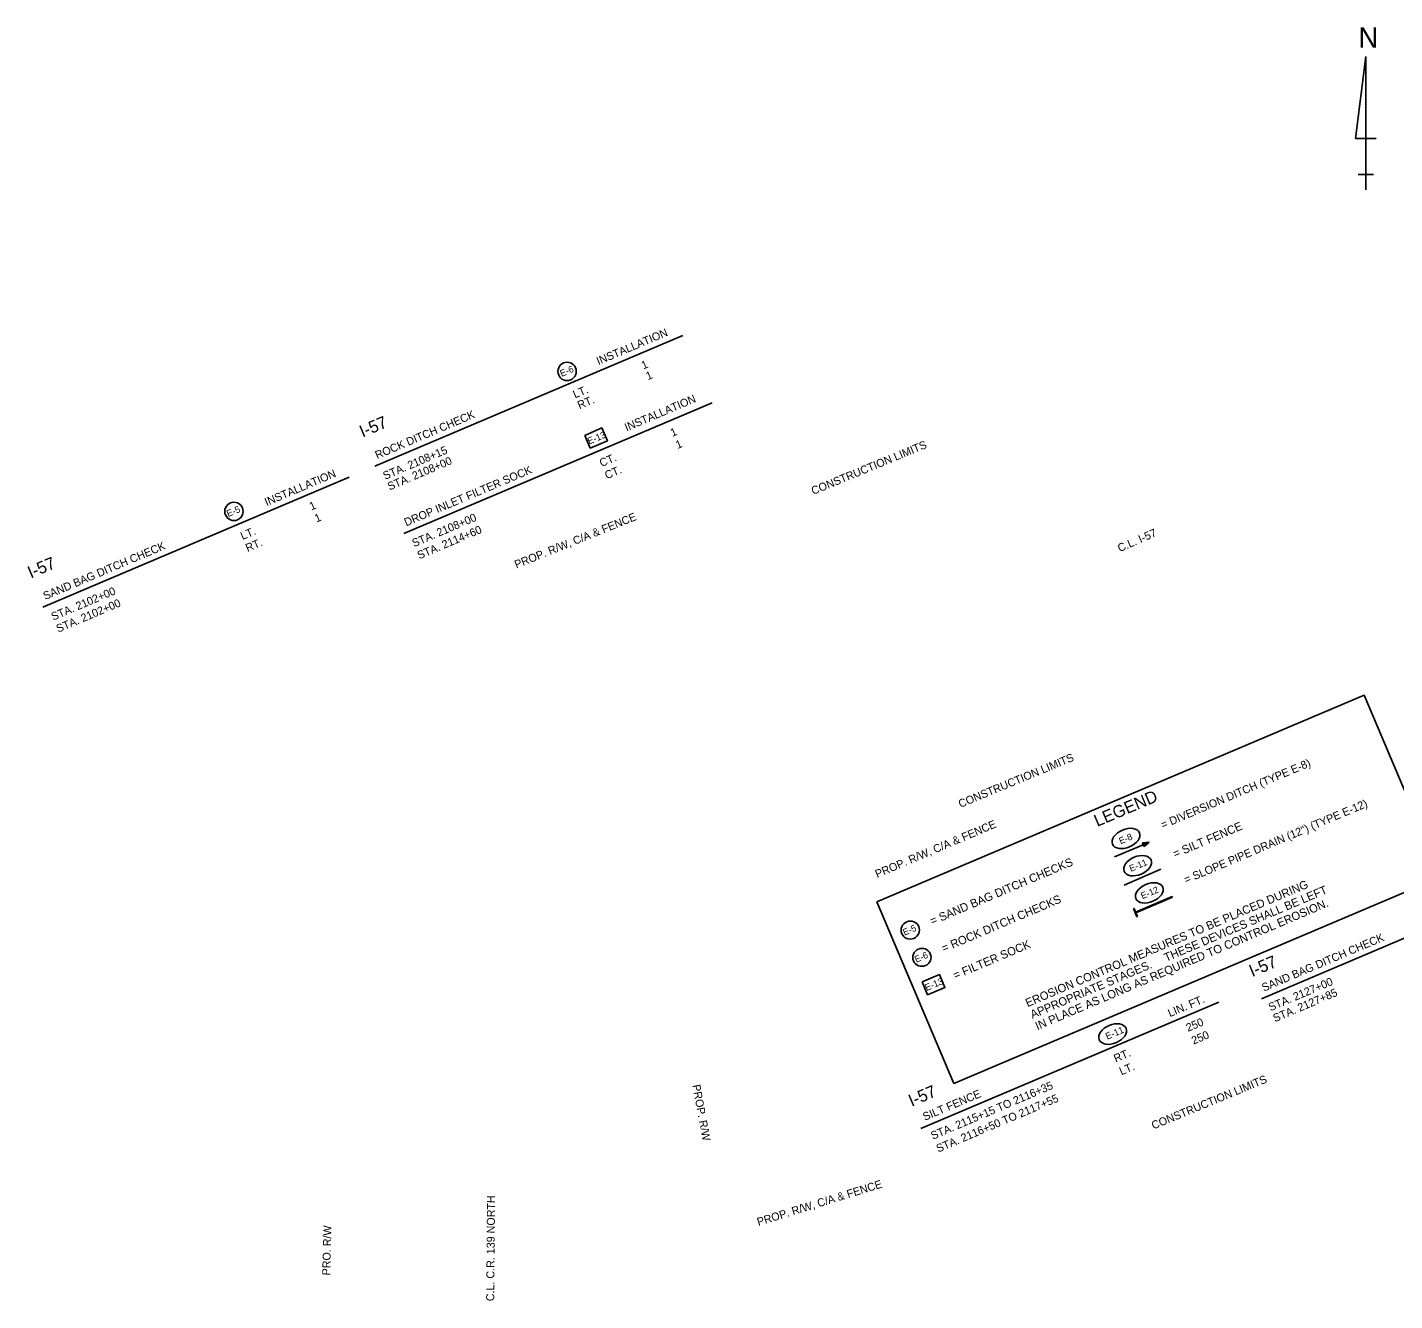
# Model space of a CAD drawing. Extents: x 1716086 to 1717910, y 765525 to 766719.
# Drawn here: x 1716086 to 1717110, y 765586 to 766541 of the extents above; entities that cross this region are included whole.
import ezdxf

# ---------------------------------------------------------------- set-up
doc = ezdxf.new("R2010")
doc.units = 0
for name, color, linetype in [('1', 7, 'Continuous'), ('44', 7, 'Continuous'), ('63', 7, 'Continuous'), ('Level 1', 7, 'Continuous'), ('Level 44', 7, 'Continuous'), ('R_Draft', 7, 'Continuous')]:
    doc.layers.add(name, color=color, linetype=linetype)

msp = doc.modelspace()

# ---------------------------------------------------------------- linework, layer by layer
at = {"layer": '1'}
for points in [[(1716503.3, 766234.8), (1716516.2, 766240.3), (1716520.3, 766230.7), (1716507.4, 766225.2)], [(1716722.2, 765885.1), (1717087.4, 766040.1), (1717145.2, 765903.9), (1716780, 765749)], [(1716756.2, 765825.1), (1716769.1, 765830.6), (1716773.2, 765821), (1716760.3, 765815.5)]]:
    msp.add_lwpolyline(points, close=True, dxfattribs=at)
for centre in [(1716490.1, 766282.7), (1716240.4, 766177.8)]:
    msp.add_circle(centre, 6.88, dxfattribs=at)
msp.add_ellipse((1716899, 765786), major_axis=(10.1, 4.3), ratio=0.638788, dxfattribs=at)
at = {"layer": '44'}
for p, q in [((1716345.9, 766211.7), (1716576.9, 766309.7)), ((1716367.7, 766161.2), (1716598.7, 766259.2)), ((1716097.1, 766106), (1716326.8, 766203.5)), ((1717010.5, 765812.4), (1717240.2, 765909.9)), ((1716755.2, 765715.2), (1716978.5, 765809.9))]:
    msp.add_line(p, q, dxfattribs=at)
at = {"layer": '63'}
for p, q in [((1717088.8, 766518.8), (1717081.1, 766457.3)), ((1717088.8, 766418.8), (1717088.8, 766518.8)), ((1717088.8, 766518.8), (1717088.8, 766441.9)), ((1717081.1, 766457.3), (1717096.5, 766457.3)), ((1717088.8, 766418.8), (1717088.8, 766441.9)), ((1717088.8, 766430.4), (1717083.1, 766430.4)), ((1717083.1, 766430.4), (1717094.6, 766430.4)), ((1717088.8, 766418.8), (1717088.8, 766430.4))]:
    msp.add_line(p, q, dxfattribs=at)
at = {"layer": 'Level 1'}
for p, q in [((1716926.4, 765929.8), (1716921.4, 765929.3)), ((1716921.4, 765929.3), (1716922.5, 765926.6)), ((1716925.1, 765929.6), (1716921.6, 765928.9)), ((1716925.2, 765929.5), (1716921.7, 765928.6)), ((1716925.2, 765929.4), (1716921.8, 765928.3)), ((1716922.1, 765927.6), (1716925.3, 765929.2)), ((1716922.3, 765927.3), (1716925.3, 765929.2)), ((1716922.4, 765927), (1716925.4, 765929.1)), ((1716922.5, 765926.6), (1716926.4, 765929.8))]:
    msp.add_line(p, q, dxfattribs=at)
msp.add_lwpolyline([(1716900.4, 765918.8), (1716924.8, 765929.2)], dxfattribs=at)
for centre, major_axis, ratio in [((1716909, 765932.6), (10.1, 4.3), 0.622952), ((1716917.7, 765912.2), (10.1, 4.3), 0.622952), ((1716926.5, 765891.8), (10.1, 4.3), 0.622952), ((1716747.3, 765863.9), (-6.33, -2.69), 0.97521), ((1716756, 765843.5), (-6.33, -2.69), 0.97521)]:
    msp.add_ellipse(centre, major_axis=major_axis, ratio=ratio, dxfattribs=at)
at = {"layer": 'Level 44'}
for p, q in [((1716943.7, 765889), (1716916.2, 765877.3)), ((1716943.9, 765888.5), (1716916.4, 765876.8)), ((1716943.7, 765889), (1716943.9, 765888.5)), ((1716914.5, 765880), (1716915, 765880.2)), ((1716917.1, 765873.8), (1716914.5, 765880)), ((1716916.2, 765877.3), (1716915, 765880.2)), ((1716917.6, 765874), (1716916.4, 765876.8)), ((1716917.1, 765873.8), (1716917.6, 765874))]:
    msp.add_line(p, q, dxfattribs=at)
msp.add_lwpolyline([(1716907.5, 765897.7), (1716935.2, 765909.5)], dxfattribs=at)

# ---------------------------------------------------------------- texts
at = {"layer": '1'}
for s, rotation, p in [('E-6 ', 23, (1716486, 766278.6)), ('E-13', 22.6177, (1716506.6, 766227.9)), ('E-5 ', 23, (1716236.1, 766173.5)), ('E-13', 22.6177, (1716759.5, 765818.2)), ('E-11', 23, (1716894.9, 765781.7))]:
    msp.add_text(s, height=5, rotation=rotation, dxfattribs=at).set_placement(p)
at = {"layer": '44'}
for s, p in [('INSTALLATION', (1716513.6, 766287.4)), ('1', (1716547.2, 766284.1)), ('1', (1716550.6, 766276.1)), ('LT.', (1716496, 766262.4)), ('INSTALLATION', (1716534.7, 766237.7)), ('RT.', (1716499.4, 766254.3)), ('ROCK DITCH CHECK', (1716347.7, 766216.9)), ('1', (1716569, 766233.6)), ('STA. 2108+15', (1716353.6, 766201.4)), ('1', (1716572.9, 766224.5)), ('STA. 2108+00', (1716357, 766193.4)), ('CT.', (1716515.9, 766211)), ('INSTALLATION', (1716264.9, 766181.7)), ('DROP INLET FILTER SOCK', (1716369.5, 766166.5)), ('CT.', (1716519.8, 766201.8)), ('1', (1716298.4, 766178.4)), ('1', (1716302.3, 766169.4)), ('STA. 2108+00', (1716375.4, 766150.9)), ('LT.', (1716246.8, 766156.3)), ('STA. 2114+60', (1716379.3, 766141.8)), ('SAND BAG DITCH CHECK', (1716098.9, 766111.3)), ('RT.', (1716250.6, 766147.3)), ('STA. 2102+00', (1716104.9, 766095.8)), ('STA. 2102+00', (1716108.7, 766086.8)), ('SAND BAG DITCH CHECK', (1717012.3, 765817.7)), ('STA. 2127+00', (1717017.3, 765803)), ('LIN. FT.', (1716941.9, 765798.6)), ('STA. 2127+85', (1717020.7, 765794.8)), ('250', (1716955.5, 765787.6)), ('250', (1716959.6, 765778)), ('RT.', (1716901.3, 765764.6)), ('LT.', (1716905.5, 765755)), ('SILT FENCE      ', (1716758.2, 765720.9)), ('STA. 2115+15 TO 2116+35', (1716764.2, 765706.7)), ('STA. 2116+50 TO 2117+55', (1716768.3, 765697.1))]:
    msp.add_text(s, height=6, rotation=23, dxfattribs=at).set_placement(p)
at = {"layer": '63'}
msp.add_text('N', height=15.4, rotation=360, dxfattribs=at).set_placement((1717083.2, 766525.3))
at = {"layer": 'Level 1'}
for s, height, rotation, p in [('= DIVERSION DITCH (TYPE E-8)', 6, 23, (1716936.6, 765939.7)), ('= SLOPE PIPE DRAIN (12") (TYPE E-12)', 6, 23, (1716954, 765898.6)), ('E-8', 4.88, 23, (1716905, 765928.2)), ('= SILT FENCE', 6.25, 23.058, (1716945.8, 765917.9)), ('= SAND BAG DITCH CHECKS', 6.25, 23.058, (1716763.7, 765867.5)), ('E-11 ', 4.88, 23.058, (1716912.7, 765907.5)), ('EROSION CONTROL MEASURES TO BE PLACED DURING', 6.25, 23.058, (1716835.2, 765806.1)), ('E-12', 4.88, 23, (1716921.3, 765887)), ('THESE DEVICES SHALL BE LEFT', 6.25, 23.058, (1716939.1, 765840.1)), ('= ROCK DITCH CHECKS', 6.25, 23.058, (1716772.4, 765847.1)), ('IN PLACE AS LONG AS REQUIRED TO CONTROL EROSION.', 6.25, 23.058, (1716842.6, 765788.8)), ('E-5 ', 4.88, 23.058, (1716743, 765859.7)), ('= FILTER SOCK', 6.25, 23, (1716781, 765826.8)), ('E-6 ', 4.88, 23.058, (1716751.8, 765839.4)), ('APPROPRIATE STAGES. ', 6.25, 23.058, (1716838.9, 765797.4))]:
    msp.add_text(s, height=height, rotation=rotation, dxfattribs=at).set_placement(p)
at = {"layer": 'Level 44'}
for s, rotation, p in [('I-57', 23, (1716336.8, 766233)), ('I-57', 23, (1716088.1, 766127.4)), ('LEGEND', 23.058, (1716887.4, 765941.2)), ('I-57', 23, (1717003.6, 765828.6)), ('I-57', 23, (1716748.3, 765731.4))]:
    msp.add_text(s, height=9.14, rotation=rotation, dxfattribs=at).set_placement(p)
at = {"layer": 'R_Draft'}
for s, rotation, p in [('CONSTRUCTION LIMITS', 22.4742, (1716674.6, 766190.1)), ('PROP. R/W, C/A & FENCE', 22.0226, (1716452.1, 766134.9)), ('C.L. I-57', 23.6531, (1716904.3, 766147.2)), ('CONSTRUCTION LIMITS', 22.5667, (1716784.9, 765955.5)), ('PROP. R/W, C/A & FENCE', 23.0701, (1716722.5, 765902.9)), ('CONSTRUCTION LIMITS', 22.5, (1716929.6, 765714.4)), ('PROP. R/W', 280.5322, (1716583.9, 765747.6)), ('PROP. R/W, C/A & FENCE', 17.2457, (1716633.5, 765642.1)), ('C.L. C.R. 139 NORTH', 89.5, (1716435.4, 765585.7)), ('PRO. R/W', 88.5681, (1716312.5, 765605))]:
    msp.add_text(s, height=6, rotation=rotation, dxfattribs=at).set_placement(p)

doc.saveas('drawing.dxf')
